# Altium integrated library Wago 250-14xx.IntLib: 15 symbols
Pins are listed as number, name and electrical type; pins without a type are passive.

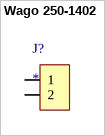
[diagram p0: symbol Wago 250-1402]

## Wago 250-1402
designator J?
footprint Wago 250-1402
pins: 1, 2


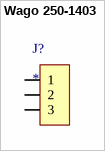
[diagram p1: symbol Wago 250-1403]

## Wago 250-1403
designator J?
footprint Wago 250-1403
pins: 1, 2, 3


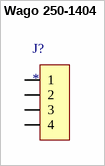
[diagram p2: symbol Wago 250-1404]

## Wago 250-1404
designator J?
footprint Wago 250-1404
pins: 1, 2, 3, 4


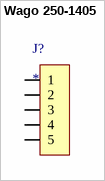
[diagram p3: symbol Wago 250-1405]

## Wago 250-1405
designator J?
footprint Wago 250-1405
pins: 1, 2, 3, 4, 5


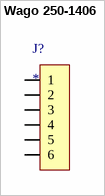
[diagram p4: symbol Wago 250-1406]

## Wago 250-1406
designator J?
footprint Wago 250-1406
pins: 1, 2, 3, 4, 5, 6


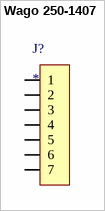
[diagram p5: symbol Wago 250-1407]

## Wago 250-1407
designator J?
footprint Wago 250-1407
pins: 1, 2, 3, 4, 5, 6, 7


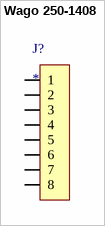
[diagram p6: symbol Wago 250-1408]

## Wago 250-1408
designator J?
footprint Wago 250-1408
pins: 1, 2, 3, 4, 5, 6, 7, 8


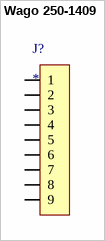
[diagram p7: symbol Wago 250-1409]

## Wago 250-1409
designator J?
footprint Wago 250-1409
pins: 1, 2, 3, 4, 5, 6, 7, 8, 9


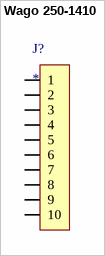
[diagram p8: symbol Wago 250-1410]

## Wago 250-1410
designator J?
footprint Wago 250-1410
pins: 1, 2, 3, 4, 5, 6, 7, 8, 9, 10


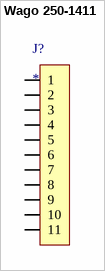
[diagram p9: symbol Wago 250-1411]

## Wago 250-1411
designator J?
footprint Wago 250-1411
pins: 1, 2, 3, 4, 5, 6, 7, 8, 9, 10, 11


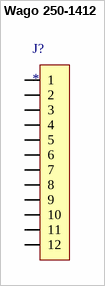
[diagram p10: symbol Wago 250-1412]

## Wago 250-1412
designator J?
footprint Wago 250-1412
pins: 1, 2, 3, 4, 5, 6, 7, 8, 9, 10, 11, 12


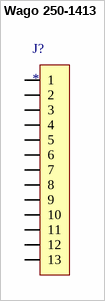
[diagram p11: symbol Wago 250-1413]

## Wago 250-1413
designator J?
footprint Wago 250-1413
pins: 1, 2, 3, 4, 5, 6, 7, 8, 9, 10, 11, 12, 13


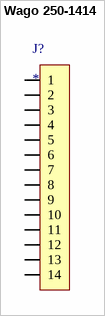
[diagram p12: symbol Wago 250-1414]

## Wago 250-1414
designator J?
footprint Wago 250-1414
pins: 1, 2, 3, 4, 5, 6, 7, 8, 9, 10, 11, 12, 13, 14


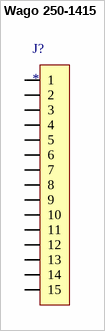
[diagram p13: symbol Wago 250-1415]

## Wago 250-1415
designator J?
footprint Wago 250-1415
pins: 1, 2, 3, 4, 5, 6, 7, 8, 9, 10, 11, 12, 13, 14, 15


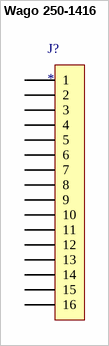
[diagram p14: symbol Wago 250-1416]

## Wago 250-1416
designator J?
footprint Wago 250-1416
pins: 1, 2, 3, 4, 5, 6, 7, 8, 9, 10, 11, 12, 13, 14, 15, 16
